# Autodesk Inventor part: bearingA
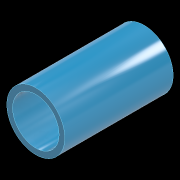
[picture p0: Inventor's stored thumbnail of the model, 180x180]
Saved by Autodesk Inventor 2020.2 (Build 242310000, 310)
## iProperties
Manager: PART
Category: 9
Company: 16
Created: 2020-10
Part Number: bearingA
Material: Generic
Document SubType Name: Modeling
Designer: Apardo
Density: 1 g/cm^3
Appearance: Sky Blue Dark
Project: PLATE ROLLING MACHINE
Cost Center: 1
Description: BEARING A
Engineer: STEEL C45
Vendor: 9
Stock Number: 1.12
Engr Approved By: D. JAEGER
Author: Apardo
Revision Number: 1.0
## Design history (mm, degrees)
sketch "Sketch1"
  geometry: C1 r 6.01 at (0, 0); C2 r 7.5 at (0, 0); 1 further point
  constraints: 2 centre point, 2 coincident
  dimensions: "d0" = 15 diameter of C2; "d1" = 12.02 diameter of C1
extrude "Extrusion1" new body sketch "Sketch1" stored distance "d2" = 28; taper "d3" = 0 deg
body "Solid1"
